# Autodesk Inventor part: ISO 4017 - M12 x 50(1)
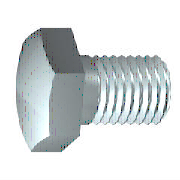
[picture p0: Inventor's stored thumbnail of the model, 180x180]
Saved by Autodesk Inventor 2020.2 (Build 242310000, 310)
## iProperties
Created: 2019-01
Part Number: ISO 4017 - M12 x 50(1)
Material: Stahl, weich
Description: Sechskantschraube
Document SubType Name: Modeling
Standard: DIN EN 24 017
Designer: lutzd
Standards Organization: DIN
Language: de-DE
Size Designation: M12 x 50
Categories: <MemberInstance><Categories><Category DisplayName="Verbindungselemente" InternalName="e4da775c-781d-43d5-af7c-5136215cf5a6" Mnemonic="FSTN"><Category DisplayNam
Mass: 60.4021 g
Surface Area: 28.6937 cm^2
Volume: 7.69454 cm^3
Density: 7.85 g/cm^3
Appearance: Halbpoliert
IsCustomPart: 0
Author: lutzd
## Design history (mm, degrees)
body "Solid1"
sketch "Skizze1"
  geometry: L1 (0, 8.315)-(0, 6); L2 (5.3, 6)-(50, 6); L3 (50, 6)-(50, 0); L4 (50, 0)-(-0.6, 0); L5 (-10.72, 0)-(60.12, 0) reference; L6 (-0.6, 0)-(-0.6, 8.315); L7 (-0.6, 8.315)-(0, 8.315); L8 (5.3, 6)-(4.226, 6); L9 (4.226, 6)-(0, 6); L10 (0, -1.663)-(0, 9.978) reference
  constraints: 16 end point, 2 collinear, 2 perpendicular, 1 parallel
  dimensions: "d0" = 50 distance between parallel lines of L3 L1 (= NLG); "d1" = 44.7 distance from line of L2.start L3 (= GEL); "d2" = 12 diameter of L2 L4 (= GD); "d9" = 0.6001 distance between parallel lines of L6 L1 (computed from SD); "d10" = 16.63 diameter of L7 L4 (= SD2); "d13" = 1.07364 distance of L2.start L8.end (computed from GAL); "d14" = 12 diameter of L9 L4 (= BDM)
workplane "Work Plane1"
revolve "Körper" stored, may be unused: angle "d12" = 90 deg
sketch "Skizze2"
  geometry: L1 (0, 10.392)-(9, 5.196); L2 (9, 5.196)-(9, -5.196); L3 (9, -5.196)-(0, -10.392); L4 (0, -10.392)-(-9, -5.196); L5 (-9, -5.196)-(-9, 5.196); L6 (-9, 5.196)-(0, 10.392); 2 further points
  constraints: 12 end point, 1 coincident, 1 vertical, 11 other
  dimensions: "d11" = 18 distance between parallel lines of L5 L2 (= SW)
extrude "Kopf" join sketch "Skizze2" distance "d3" = 6.9 (= KOH - SD); taper "d4" = 0 deg
sketch "Skizze4"
  geometry: L1 (-7.5, 9)-(-7.5, 10.392); L2 (-7.5, 10.392)-(-6.696, 10.392); L3 (-6.696, 10.392)-(-7.5, 9); L4 (-8.88, 0)-(0.78, 0) reference; L5 (-0.6, 10.392)-(-7.5, 10.392) reference; L6 (-7.5, 5.196)-(-7.5, 10.392) reference
  constraints: 6 end point, 2 collinear, 1 perpendicular, 1 vertical
  dimensions: "d5" = 30 deg angle of L3 L1 (= ANG1); "d19" = 18 diameter of L1.start L4 (= SW0)
revolve "Fase1" stored, may be unused: angle "d21" = 90 deg
feature "Gewinde" dims "d15" = 44.7 (= GEL), "d16" = 0
chamfer "Fase2" distance "d6" = 1.07354 (= -0.5 x SPD + 0.5 x GD); stored, may be unused: second distance "d7" = 1.07364 (computed from GUL), angle "d55" = 45 deg
other parameters: "NLG" = 50 [user parameter; used in 1 equation term], "GD" = 12 (= NND) [user parameter; used in 2 equation terms], "BDM" = 12 (= NND) [user parameter; used in 1 equation term], "KOH" = 7.5 [user parameter; used in 1 equation term], "GEL" = 44.7 [user parameter; used in 2 equation terms], "SW" = 18 [user parameter; used in 2 equation terms], "SW0" = 18 (= SW) [user parameter; used in 1 equation term], "SPD" = 9.85293 (= NND - 1.2269 x PTC) [user parameter; used in 1 equation term], "SD2" = 16.63 [user parameter; used in 2 equation terms], "SD" = 0.6 [user parameter; used in 2 equation terms], "ANG1" = 30 deg [user parameter; used in 1 equation term], "GAL" = 1.07354 (= 0.61345 x PTC) [user parameter; used in 1 equation term], "GUL" = 1.07354 (= 0.61345 x PTC) [user parameter; used in 1 equation term], "d8" = 0, "RR" = 0.6 [user parameter], "d57" = 0, "d58" = 0, "TPU" = 5.71429 (computed from PTC) [user parameter], "GD1" = 9.85293 (= THREADDIA - 1.2269 x PTC) [user parameter], "THREADDIA" = 12 [user parameter; used in 1 equation term], "SDH" = 16.63 (= SD2) [user parameter], "SDHG" = 5.3 [user parameter], "TOA" = 30 deg [user parameter], "PTC" = 1.75 [user parameter; used in 5 equation terms], "NND" = 12 [user parameter; used in 3 equation terms], "E0" = 20.79 [user parameter]
